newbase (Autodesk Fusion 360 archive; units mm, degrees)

design "newbase" references "arrayledrgbcircle"
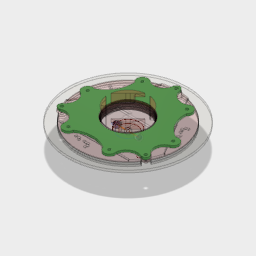
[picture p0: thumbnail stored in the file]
sketch "primary" plane through (0, 0, 0) normal (0, 1, 0) x axis (1, 0, 0)
  circle C1 centre (0, 0) radius 80
  circle C2 centre (0, 0) radius 27.5
  circle C3 centre (0, 0) radius 67
  circle C4 centre (0, 65) radius 1.6
  circle C5 centre (0, 65) radius 5
  circle C6 centre (-56.2917, -32.5) radius 5
  circle C7 centre (-56.2917, -32.5) radius 1.6
  circle C8 centre (56.2917, -32.5) radius 5
  circle C9 centre (56.2917, -32.5) radius 1.6
  point P4 (0, 0)
  point P5 (0, 65)
  dimension "d1" diameter C1 = 160
  dimension "d2" diameter C2 = 55
  dimension "d3" diameter C3 = 134
  dimension "d4" diameter C4 = 3.2
  dimension "d5" diameter C5 = 10
  dimension "d8" distance P4 P5 = 65
  dimension "d7" C-Pattern1-Angle = 360
extrude "Extrude1" new body sketch "primary" profile of C2 C3 C4 C5 C6 C7 C8 C9 along normal blind 5
extrude "Extrude1" new body sketch "primary" profile of C1 C3 C4 C5 C6 C7 C8 C9 against normal blind 3
component_from_bodies "Body->Comp"
component_insert "Component Insert"
position "Position1"
extrude "Extrude2" cut of existing geometry blind -1
position "Position2"
step "C-Pattern" TotalAngle 360
combine "Combine1"
extrude "Extrude3" add of existing geometry blind 1
extrude "Extrude4" cut of existing geometry blind -2
extrude "Extrude5" cut of existing geometry blind -2
extrude "Extrude6" cut of existing geometry blind -2
extrude "Extrude7" cut of existing geometry blind -2
extrude "Extrude8" cut of existing geometry blind -2
extrude "Extrude9" cut of existing geometry blind -2
extrude "Extrude10" cut of existing geometry blind -2
extrude "Extrude11" cut of existing geometry blind -2
extrude "Extrude12" cut of existing geometry blind -2
extrude "Extrude13" cut of existing geometry blind -2
extrude "Extrude14" cut of existing geometry blind -2
extrude "Extrude15" add of existing geometry blind 4 taper -15
extrude "Extrude16" cut of existing geometry blind 3 taper 50
extrude "Extrude17" cut of existing geometry blind -1.8
extrude "Extrude18" cut of existing geometry blind 1.8 taper -5
extrude "Extrude19" add of existing geometry blind 1.8 taper -10
sketch "innersplat" plane through (0, 5, 0) normal (0, 1, 0) x axis (-1, 0, 0)
  line L1 (64.1697, 18.1334) -> (62.973, 17.7903)
  line L2 (44.7956, 47.2415) -> (45.8929, 48.3778)
  line L3 (-46.8933, 45.6411) -> (44.7956, 47.2415)
  line L4 (-47.7888, 46.5059) -> (-46.8933, 45.6411)
  line L5 (-63.3102, 15.1734) -> (-64.8429, 15.5555)
  line L6 (-16.0797, -63.4314) -> (-63.3102, 15.1734)
  line L7 (-16.3808, -64.6393) -> (-16.0797, -63.4314)
  line L8 (18.5146, -62.4149) -> (18.9499, -63.9333)
  line L9 (62.973, 17.7903) -> (18.5146, -62.4149)
  line L10 (-16.4194, -63.4821) -> (-16.7651, -64.8686)
  line L11 (-63.5145, 14.8972) -> (-16.4194, -63.4821)
  line L12 (-65.2242, 15.3235) -> (-63.5145, 14.8972)
  line L13 (53.3921, 56.6004) -> (44.6586, 47.5566)
  line L14 (-46.7674, 45.9607) -> (-55.8112, 54.6942)
  line L15 (44.6586, 47.5566) -> (-46.7674, 45.9607)
  line L16 (-27.8174, 0) -> (0, 0)
  circle C1 centre (-56.2917, 32.5) radius 1.9174
  circle C2 centre (0, -65) radius 1.9174
  circle C3 centre (0, 0) radius 27.8174
  circle C4 centre (56.2917, 32.5) radius 1.9174
  arc A1 centre (0, 0) radius 66.6826 clockwise from (59.8334, 29.4369) to (64.1697, 18.1334)
  arc A2 centre (56.2917, 32.5) radius 4.6826 clockwise from (55.4098, 37.0988) to (59.8334, 29.4369)
  arc A3 centre (0, 0) radius 66.6826 clockwise from (45.8929, 48.3778) to (55.4098, 37.0988)
  arc A4 centre (0, 0) radius 66.6826 clockwise from (-55.4098, 37.0988) to (-47.7888, 46.5059)
  arc A5 centre (-56.2917, 32.5) radius 4.6826 clockwise from (-59.8334, 29.4369) to (-55.4098, 37.0988)
  arc A6 centre (0, 0) radius 66.6826 clockwise from (-64.8429, 15.5555) to (-59.8334, 29.4369)
  arc A7 centre (0, 0) radius 66.6826 clockwise from (-4.4236, -66.5357) to (-16.3808, -64.6393)
  arc A8 centre (0, -65) radius 4.6826 clockwise from (4.4236, -66.5357) to (-4.4236, -66.5357)
  arc A9 centre (0, 0) radius 66.6826 clockwise from (18.9499, -63.9333) to (4.4236, -66.5357)
  circle C5 centre (-26.0224, 50.8955) radius 7.5
  circle C6 centre (28.0714, 51.8397) radius 7.5
  circle C7 centre (-26.0224, 50.8955) radius 0.7062
  circle C8 centre (28.0714, 51.8397) radius 0.7062
  arc A10 centre (0.7926, 81.7658) radius 35.287 clockwise from (20.6067, 52.567) to (-18.6598, 52.3248)
  arc A11 centre (48.4412, 48.8033) radius 13.0949 clockwise from (54.1224, 37.0049) to (35.4894, 50.734)
  arc A12 centre (56.2917, 32.5) radius 5 clockwise from (60.2087, 29.3924) to (55.5589, 37.446)
  circle C9 centre (56.2917, 32.5) radius 5
  arc A13 centre (-56.2917, 32.5) radius 5 clockwise from (-55.5589, 37.446) to (-60.2087, 29.3924)
  arc A14 centre (-0.2565, 1.0456) radius 77.2302 clockwise from (-55.8112, 54.6942) to (53.3921, 56.6004)
  arc A15 centre (-48.1837, 50.7217) radius 14.9837 clockwise from (-33.293, 49.0548) to (-53.7741, 36.8199)
  arc A16 centre (-66.4855, 17.5497) radius 13.0949 clockwise from (-59.1084, 28.3689) to (-61.6816, 5.3677)
  circle C10 centre (-58.9302, -1.6094) radius 7.5
  arc A17 centre (-71.2075, -40.1965) radius 35.287 clockwise from (-55.8277, -8.4376) to (-35.9847, -42.3223)
  circle C11 centre (-31.0656, -47.9838) radius 7.5
  arc A18 centre (-19.8344, -67.0892) radius 14.9837 clockwise from (-25.8362, -53.36) to (-5, -64.9797)
  arc A19 centre (18.0443, -66.3529) radius 13.0949 clockwise from (4.986, -65.3738) to (26.1922, -56.1017)
  circle C12 centre (30.8589, -50.2304) radius 7.5
  arc A20 centre (70.415, -41.5693) radius 35.287 clockwise from (35.221, -44.1294) to (54.6445, -10.0025)
  circle C13 centre (57.088, -2.9117) radius 7.5
  arc A21 centre (68.0182, 16.3675) radius 14.9837 clockwise from (59.1292, 4.3052) to (58.774, 28.1597)
  circle C14 centre (30.8589, -50.2304) radius 1.778
  circle C15 centre (30.8589, -50.2304) radius 1.778
  arc A22 centre (-50.2895, -30.7888) radius 1.6618 clockwise from (-48.6559, -31.0934) to (-49.2638, -29.4814)
  arc A23 centre (-47.6302, -29.7859) radius 1.6618 clockwise from (-49.2638, -29.4814) to (-48.6559, -31.0934)
  arc A24 centre (-46.1884, -26.549) radius 1.6618 clockwise from (-46.0195, -24.8959) to (-47.8458, -26.4296)
  arc A25 centre (-47.6769, -24.7765) radius 1.6618 clockwise from (-47.8458, -26.4296) to (-48.5753, -23.3785)
  arc A26 centre (-48.7679, -21.7279) radius 1.6618 clockwise from (-48.5753, -23.3785) to (-47.8695, -23.126)
  arc A27 centre (-47.6769, -24.7765) radius 1.6618 clockwise from (-47.8695, -23.126) to (-46.0195, -24.8959)
  arc A28 centre (-52.9742, -17.4399) radius 1.6618 clockwise from (-51.611, -16.4895) to (-53.2282, -15.7977)
  arc A29 centre (-51.865, -14.8473) radius 1.6618 clockwise from (-53.2282, -15.7977) to (-51.611, -16.4895)
  circle C16 centre (-54.067, -11.4292) radius 1.6618
  arc A30 centre (0, 0) radius 67 clockwise from (-16.7651, -64.8686) to (-65.2242, 15.3235)
  circle C17 centre (-31.0656, -47.9838) radius 1.778
  circle C18 centre (-58.9302, -1.6094) radius 1.778
  circle C19 centre (-58.9302, -1.6094) radius 1.778
  circle C20 centre (0.1021, 53.2748) radius 0.47
  circle C21 centre (-1.9803, 56.1419) radius 0.47
  circle C22 centre (17.1355, 52.538) radius 0.47
  circle C23 centre (25.0284, 71.6947) radius 0.4955
  circle C24 centre (-0.8872, 73.5627) radius 0.47
  circle C25 centre (39.8169, 62.9684) radius 0.4955
  circle C26 centre (-22.8865, 67.7168) radius 0.47
  circle C27 centre (14.1431, 71.1576) radius 0.47
  circle C28 centre (37.5528, 65.8764) radius 0.4955
  circle C29 centre (-4.7526, 69.4306) radius 0.47
  circle C30 centre (-3.2754, 72.1238) radius 0.47
  circle C31 centre (-39.6032, 63.8855) radius 0.4955
  circle C32 centre (-32.038, 68.0652) radius 0.47
  circle C33 centre (-24.5993, 71.2435) radius 0.47
  circle C34 centre (6.7317, 73.6956) radius 0.47
  circle C35 centre (-46.2367, 51.9399) radius 0.47
  circle C36 centre (5.567, 53.0982) radius 0.47
  circle C37 centre (-43.1288, 62.1717) radius 0.4955
  circle C38 centre (-7.7707, 74.9667) radius 0.47
  circle C39 centre (-16.8801, 72.9024) radius 0.47
  circle C40 centre (-45.3191, 57.5838) radius 0.47
  circle C41 centre (16.0006, 71.317) radius 0.47
  circle C42 centre (-18.9678, 68.8014) radius 0.47
  circle C43 centre (23.2075, 68.5214) radius 0.4955
  circle C44 centre (11.3837, 54.5969) radius 0.47
  circle C45 centre (4.5303, 73.8722) radius 0.47
  circle C46 centre (47.2705, 58.0178) radius 0.4955
  circle C47 centre (31.5441, 65.5194) radius 0.4955
  circle C48 centre (-15.5504, 69.4961) radius 0.47
  circle C49 centre (45.2831, 55.4427) radius 0.4955
  circle C50 centre (13.0743, 52.3401) radius 0.47
  circle C51 centre (2.3814, 53.6777) radius 0.47
  circle C52 centre (-1.5192, 58.9464) radius 0.47
  circle C53 centre (28.0714, 51.8397) radius 1.778
  circle C54 centre (-26.0224, 50.8955) radius 1.778
  arc A31 centre (-0.2565, 1.0456) radius 77.2302 clockwise from (-55.8112, 54.6942) to (53.3921, 56.6004)
  circle C55 centre (28.0714, 51.8397) radius 1.778
  circle C56 centre (57.088, -2.9117) radius 1.778
  circle C57 centre (0, -65) radius 5
  dimension "d51" diameter C6 = 15
  dimension "d52" diameter C5 = 15
  dimension "d54" C-Pattern1-Angle = 360
extrude "Extrude1" new body sketch "innersplat" profile of C1 C2 C3 C4 A1 A2 A3 L3 A4 A5 A6 L6 L7 A7 A8 A9 L8 L9 C5 C6 A10 A11 A12 C9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 along normal blind 3
extrude "Extrude2" cut sketch "innersplat" profile of L6 L7 A7 A9 L8 L9 A16 A18 A19 C57 along normal blind 3
position "Position3"
combine "Combine2"
extrude "Extrude20" cut sketch "primary" profile of C2 C3 C5 C6 C8 along normal blind 2
place_component sketch "primary"
extrude "Extrude1" new body sketch "primary" profile of C2 C3 C5 C6 C8 against normal blind 3
sketch "Sketch1" plane through (0, 0, 0) normal (0, 1, 0) x axis (1, 0, 0)
  line L1 (-20.95, -20.95) -> (20.95, -20.95)
  line L2 (-20.95, 20.95) -> (-20.95, -20.95)
  line L3 (20.95, 20.95) -> (-20.95, 20.95)
  line L4 (20.95, -20.95) -> (20.95, 20.95)
  line L5 (-20.95, 20.95) -> (20.95, -20.95)
  line L6 (20.95, 20.95) -> (-20.95, -20.95)
  line L7 (20.95, 16.85) -> (16.85, 20.95)
  line L8 (-16.85, -20.95) -> (-20.95, -16.85)
  line L9 (0, -20.95) -> (0, 20.95)
  line L10 (16.85, -20.95) -> (20.95, -16.85)
  line L11 (-20.95, 16.85) -> (-16.85, 20.95)
  line L12 (-1.9, -1.6248) -> (-1.9, 1.6248)
  circle C1 centre (14.8, 14.8) radius 2.05
  circle C2 centre (0, 0) radius 11
  circle C3 centre (-14.8, 14.8) radius 2.05
  circle C4 centre (-14.8, -14.8) radius 2.05
  circle C5 centre (14.8, -14.8) radius 2.05
  circle C6 centre (0, 0) radius 4.5
  circle C7 centre (0, 0) radius 2.5
  point P2 (20.95, -20.95)
  point P3 (-20.95, -20.95)
  point P5 (20.95, 20.95)
  point P7 (14.8, 14.8)
  point P13 (20.95, 16.85)
  point P22 (0, 0)
  dimension "d1_2" distance P2 P3 = 41.9
  dimension "d2_2" distance P2 P5 = 41.9
  dimension "d3_2" diameter C1 = 4.1
  dimension "d4_2" distance L4 P7 = 6.15
  dimension "d5_2" diameter C2 = 22
  dimension "d8_2" distance L3 P13 = 4.1
  dimension "d9_2" diameter C6 = 9
  dimension "d10_2" diameter C7 = 5
  dimension "d11_2" distance P22 L12 = 1.9
  dimension "d7_2" C-Pattern1-Angle = 360
extrude "Extrude1" new body sketch "Sketch1" profile of L1 L2 L3 L4 C1 C2 C3 C4 C5 L7 L8 L10 L11 along normal blind 8 named "d12_2"
extrude "Extrude2" add sketch "Sketch1" profile of C2 C6 along normal blind 10 named "d14_2"
extrude "Extrude3" new body sketch "Sketch1" profile of C7 L12 along normal blind 22.3 named "d16_2"
extrude "Extrude4" add sketch "Sketch1" profile of C7 L12 along normal blind 11 named "d18_2"
extrude "Extrude5" add sketch "Sketch1" profile of C6 C7 along normal blind 7 named "d20_2"
extrude "Extrude6" add of existing geometry blind 10 named "d22_2"
sketch "Sketch2" plane through (0, 0, 0) normal (0, 1, 0) x axis (1, 0, 0)
  line L1 (-20.95, -20.95) -> (20.95, -20.95)
  line L2 (20.95, -20.95) -> (20.95, 20.95)
  line L3 (20.95, 16.85) -> (20.95, -16.85)
  line L4 (20.95, -16.85) -> (20.95, 16.85)
  line L5 (20.95, -14.0216) -> (14.0216, -20.95)
  line L6 (16.85, -20.95) -> (20.95, -16.85)
  line L7 (20.95, 20.95) -> (-20.95, -20.95)
  line L8 (0, -20.95) -> (0, 20.95)
  line L9 (0, 19) -> (0, -20.95)
  line L10 (-14.0216, 20.95) -> (-20.95, 14.0216)
  line L11 (14.0216, 20.95) -> (20.95, 14.0216)
  line L12 (-20.95, -14.0216) -> (-14.0216, -20.95)
  line L13 (-20.95, -14.0216) -> (-20.95, 14.0216)
  line L14 (14.0216, -20.95) -> (-14.0216, -20.95)
  line L15 (20.95, 14.0216) -> (20.95, -14.0216)
  line L16 (-14.0216, 20.95) -> (14.0216, 20.95)
  dimension "d24_2" angle L1 L5 = 45
  dimension "d25_2" distance L5 L6 = 2
extrude "Extrude7" add sketch "Sketch2" profile of L1 L2 L3 L4 L5 L8 L10 L11 L12 L13 L14 L15 L16 against normal blind 30 named "d26_2"
work_plane "WorkPlane1" sketch "Sketch1" AlongDistance -15 named "d28_2"
split "Split1"
sketch "Sketch3" plane through (0, -15, 0) normal (0, 1, 0) x axis (1, 0, 0)
  line L1 (0, 35) -> (0, -30)
copy_paste_bodies "CopyPasteBodies1"
move "Move1" RotateAngle 180 named "d29_2"
work_plane "WorkPlane2" AlongDistance 0 named "d30_2"
combine "Combine1"
combine "Combine2"
combine "Combine3"
combine "Combine4"
sketch "Sketch4" plane through (0, -38, 0) normal (0, -1, 0) x axis (1, 0, 0)
  circle C1 centre (0, 0) radius 19.3452
extrude "Extrude8" cut sketch "Sketch4" along normal blind 30 named "d31_2"
sketch "Sketch5" plane through (0, 0, -20.95) normal (0, 0, -1) x axis (-1, 0, 0)
  line L1 (-16.85, -30) -> (-14.0216, -30)
  line L2 (-16.85, -38) -> (-16.85, -30)
  line L3 (16.85, -38) -> (-16.85, -38)
  line L4 (16.85, -30) -> (16.85, -38)
  line L5 (14.0216, -30) -> (16.85, -30)
  line L6 (14.0216, 0) -> (14.0216, -30)
  line L7 (16.85, 0) -> (14.0216, 0)
  line L8 (16.85, 8) -> (16.85, 0)
  line L9 (-16.85, 8) -> (16.85, 8)
  line L10 (-16.85, 0) -> (-16.85, 8)
  line L11 (-14.0216, 0) -> (-16.85, 0)
  line L12 (-14.0216, -30) -> (-14.0216, 0)
  line L13 (3.75, -30) -> (-3.75, -30)
  line L14 (3.75, -37.5) -> (3.75, -30)
  line L15 (-3.75, -37.5) -> (3.75, -37.5)
  line L16 (-3.75, -30) -> (-3.75, -37.5)
  line L17 (14.0216, -30) -> (-14.0216, -30)
  line L18 (0, -30) -> (0, -37.5)
  point P14 (-3.75, -30)
  point P15 (3.75, -30)
  point P16 (3.75, -37.5)
  dimension "d33_2" distance P14 P15 = 7.5
  dimension "d34_2" distance P15 P16 = 7.5
  dimension "d35_2" distance L3 L15 = 0.5
  dimension "d38_2" distance L4 L14 = 13.1
  dimension "d39_2" = 13.2
extrude "Extrude9" cut sketch "Sketch5" profile of L13 L14 L15 L16 against normal blind 1 named "d40_2"
revolve "Revolve1" AlongAngle 90
extrude "Extrude1" cut of existing geometry blind 235
position "Position4"
sketch "Sketch6" plane through (0, -3, 0) normal (0, -1, 0) x axis (1, 0, 0)
  line L1 (2.8991, -26.7286) -> (26.7286, -2.8991)
  line L2 (26.7286, -2.8991) -> (2.8991, -26.7286)
  line L3 (26.7286, -2.8991) -> (2.8991, -26.7286)
  line L4 (2.8991, 26.7286) -> (26.7286, 2.8991)
  line L5 (2.8991, 26.7286) -> (-2.8991, 26.7286)
  line L6 (-2.8991, 26.7286) -> (2.8991, 26.7286)
  line L7 (-29.6278, 0) -> (0, 29.6278)
  line L8 (-2.8991, 26.7286) -> (-26.7286, 2.8991)
  line L9 (-2.8991, -26.7286) -> (-26.7286, -2.8991)
  circle C1 centre (0, 0) radius 27.5
  arc A1 centre (0, 0) radius 67 clockwise from (-4.6497, -66.8385) to (-60.2087, 29.3924)
  arc A2 centre (0, -65) radius 5 clockwise from (-4.6497, -66.8385) to (4.6497, -66.8385)
  arc A3 centre (0, 0) radius 67 clockwise from (60.2087, 29.3924) to (4.6497, -66.8385)
  arc A4 centre (56.2917, 32.5) radius 5 clockwise from (60.2087, 29.3924) to (55.5589, 37.446)
  arc A5 centre (0, 0) radius 67 clockwise from (-55.5589, 37.446) to (55.5589, 37.446)
  arc A6 centre (-56.2917, 32.5) radius 5 clockwise from (-55.5589, 37.446) to (-60.2087, 29.3924)
  circle C2 centre (0, 0) radius 26.5
  circle C3 centre (0, 0) radius 21.0524
  dimension "d75" diameter C2 = 53
extrude "Extrude1" new body sketch "Sketch6" profile of C2 C3 L1 L2 L3 L4 L7 L8 L9 against normal blind 23
remove_instance "RemoveInstance1"
sketch "Sketch7" plane through (-24.7286, 0, 0) normal (-1, 0, 0) x axis (0, 0, 1)
  line L1 (-4.8991, 16) -> (-4.8991, 46)
  line L2 (4.8991, 16) -> (-4.8991, 16)
  line L3 (4.8991, 46) -> (4.8991, 16)
  line L4 (-4.8991, 46) -> (4.8991, 46)
  line L5 (13.3474, 20) -> (13.3474, -3)
  line L6 (13.3474, 16) -> (-4.8991, 16)
  line L7 (13.3474, 8) -> (13.3474, 16)
  line L8 (-26.7286, 8) -> (-2.8991, 8)
  line L9 (-4.8991, 8) -> (13.3474, 8)
  line L10 (-4.8991, 16) -> (-4.8991, 8)
  line L11 (4.2241, 8) -> (4.2241, 16)
  line L12 (5.7241, 8) -> (5.7241, 16)
  point P16 (5.7241, 16)
  point P17 (5.7241, 8)
  dimension "d78" distance P16 P17 = 8
  dimension "d79" distance L11 L12 = 1.5
revolve "Revolve1" sketch "Sketch7" AlongAngle 360
circular_pattern "C-Pattern1" TotalAngle 360
combine "Combine1"
combine "Combine2"
combine "Combine3"
combine "Combine4"
combine "Combine5"
extrude "Extrude2" cut of existing geometry blind -3
extrude "Extrude3" cut of existing geometry blind -3
extrude "Extrude4" cut of existing geometry blind -3
extrude "Extrude5" cut of existing geometry blind -3
extrude "Extrude6" add sketch "innersplat" profile of C3 along normal blind 3 and against normal blind 11
sketch "Sketch8" plane through (0, 0, 0) normal (1, 0, 0) x axis (0, 0, -1)
  line L1 (66.8385, -3) -> (-29.3924, -3)
  line L2 (-37.446, -3) -> (-27.5, -3)
  line L3 (-37.5287, -3) -> (-27.5287, -3)
  line L4 (-36, -6) -> (-37.5287, -3)
  line L5 (27.8174, -6) -> (-27.8174, -6)
  line L6 (-27.5199, -6) -> (-36, -6)
  line L7 (-27.5287, -3) -> (-27.5199, -6)
  point P6 (-27.5287, -3)
  point P7 (-37.5287, -3)
  dimension "d95" distance P6 P7 = 10
revolve "Revolve2" sketch "Sketch8" AlongAngle 360
thread "Thread1"
sketch "Innersplat.dxf" plane through (0, 8, 0) normal (0, 1, 0) x axis (-1, 0, 0)
  arc A1 centre (18.0443, -66.3529) radius 13.0949 clockwise from (4.986, -65.3738) to (26.1922, -56.1017)
  arc A2 centre (30.8589, -50.2304) radius 7.5 clockwise from (35.221, -44.1294) to (26.1922, -56.1017)
  arc A3 centre (70.415, -41.5693) radius 35.287 clockwise from (35.221, -44.1294) to (54.6445, -10.0025)
  arc A4 centre (57.088, -2.9117) radius 7.5 clockwise from (59.1292, 4.3052) to (54.6445, -10.0025)
  arc A5 centre (68.0182, 16.3675) radius 14.9837 clockwise from (59.1292, 4.3052) to (58.774, 28.1597)
  arc A6 centre (56.2917, 32.5) radius 5 clockwise from (59.9841, 29.1287) to (58.774, 28.1597)
  arc A7 centre (0, 0) radius 66.6826 clockwise from (59.8334, 29.4369) to (59.9841, 29.1287)
  arc A8 centre (56.2917, 32.5) radius 4.6826 clockwise from (55.4098, 37.0988) to (59.8334, 29.4369)
  arc A9 centre (0, 0) radius 66.6826 clockwise from (55.2182, 37.3834) to (55.4098, 37.0988)
  arc A10 centre (56.2917, 32.5) radius 5 clockwise from (54.1224, 37.0049) to (55.2182, 37.3834)
  arc A11 centre (48.4412, 48.8033) radius 13.0949 clockwise from (54.1224, 37.0049) to (35.4894, 50.734)
  arc A12 centre (28.0714, 51.8397) radius 7.5 clockwise from (20.6067, 52.567) to (35.4894, 50.734)
  arc A13 centre (0.7926, 81.7658) radius 35.287 clockwise from (20.6067, 52.567) to (-18.6598, 52.3248)
  arc A14 centre (-26.0224, 50.8955) radius 7.5 clockwise from (-33.293, 49.0548) to (-18.6598, 52.3248)
  arc A15 centre (-48.1837, 50.7217) radius 14.9837 clockwise from (-33.293, 49.0548) to (-53.7741, 36.8199)
  arc A16 centre (-56.2917, 32.5) radius 5 clockwise from (-55.2182, 37.3834) to (-53.7741, 36.8199)
  arc A17 centre (0, 0) radius 66.6826 clockwise from (-55.4098, 37.0988) to (-55.2182, 37.3834)
  arc A18 centre (-56.2917, 32.5) radius 4.6826 clockwise from (-59.8334, 29.4369) to (-55.4098, 37.0988)
  arc A19 centre (0, 0) radius 66.6826 clockwise from (-59.9841, 29.1287) to (-59.8334, 29.4369)
  arc A20 centre (-56.2917, 32.5) radius 5 clockwise from (-59.1084, 28.3689) to (-59.9841, 29.1287)
  arc A21 centre (-66.4855, 17.5497) radius 13.0949 clockwise from (-59.1084, 28.3689) to (-61.6816, 5.3677)
  arc A22 centre (-58.9302, -1.6094) radius 7.5 clockwise from (-55.8277, -8.4376) to (-61.6816, 5.3677)
  arc A23 centre (-71.2075, -40.1965) radius 35.287 clockwise from (-55.8277, -8.4376) to (-35.9847, -42.3223)
  arc A24 centre (-31.0656, -47.9838) radius 7.5 clockwise from (-25.8362, -53.36) to (-35.9847, -42.3223)
  arc A25 centre (-19.8344, -67.0892) radius 14.9837 clockwise from (-25.8362, -53.36) to (-5, -64.9797)
  arc A26 centre (0, -65) radius 5 clockwise from (-4.7659, -66.5121) to (-5, -64.9797)
  arc A27 centre (0, 0) radius 66.6826 clockwise from (-4.4236, -66.5357) to (-4.7659, -66.5121)
  arc A28 centre (0, -65) radius 4.6826 clockwise from (4.4236, -66.5357) to (-4.4236, -66.5357)
  arc A29 centre (0, 0) radius 66.6826 clockwise from (4.7659, -66.5121) to (4.4236, -66.5357)
  arc A30 centre (0, -65) radius 5 clockwise from (4.986, -65.3738) to (4.7659, -66.5121)
  circle C1 centre (30.8589, -50.2304) radius 1.778
  circle C2 centre (56.2917, 32.5) radius 1.9174
  circle C3 centre (-56.2917, 32.5) radius 1.9174
  circle C4 centre (0, 0) radius 27.8174
  circle C5 centre (28.0714, 51.8397) radius 1.778
  circle C6 centre (57.088, -2.9117) radius 1.778
  circle C7 centre (0, -65) radius 1.9174
  circle C8 centre (-31.0656, -47.9838) radius 1.778
  circle C9 centre (-58.9302, -1.6094) radius 1.778
  circle C10 centre (-26.0224, 50.8955) radius 1.778
sketch "Outerring.dxf" plane through (0, 2, 0) normal (0, 1, 0) x axis (-1, 0, 0)
  circle C1 centre (0, -65) radius 1.6
  circle C2 centre (56.2917, 32.5) radius 1.6
  arc A1 centre (0, 0) radius 67 clockwise from (60.2087, 29.3924) to (4.6497, -66.8385)
  arc A2 centre (0, -65) radius 5 clockwise from (-4.6497, -66.8385) to (4.6497, -66.8385)
  arc A3 centre (0, 0) radius 67 clockwise from (-4.6497, -66.8385) to (-60.2087, 29.3924)
  arc A4 centre (-56.2917, 32.5) radius 5 clockwise from (-55.5589, 37.446) to (-60.2087, 29.3924)
  arc A5 centre (0, 0) radius 67 clockwise from (-55.5589, 37.446) to (55.5589, 37.446)
  arc A6 centre (56.2917, 32.5) radius 5 clockwise from (60.2087, 29.3924) to (55.5589, 37.446)
  circle C3 centre (-56.2917, 32.5) radius 1.6
  circle C4 centre (0, 0) radius 80
sketch "Decoring.dxf" plane through (0, 0, 0) normal (0, 1, 0) x axis (-1, 0, 0)
  circle C1 centre (0, 0) radius 27.5
  arc A1 centre (0, 0) radius 67 clockwise from (60.2087, 29.3924) to (4.6497, -66.8385)
  arc A2 centre (56.2917, 32.5) radius 5 clockwise from (60.2087, 29.3924) to (55.5589, 37.446)
  arc A3 centre (0, 0) radius 67 clockwise from (-55.5589, 37.446) to (55.5589, 37.446)
  arc A4 centre (-56.2917, 32.5) radius 5 clockwise from (-55.5589, 37.446) to (-60.2087, 29.3924)
  arc A5 centre (0, 0) radius 67 clockwise from (-4.6497, -66.8385) to (-60.2087, 29.3924)
  arc A6 centre (0, -65) radius 5 clockwise from (-4.6497, -66.8385) to (4.6497, -66.8385)
sketch "Sketch12" plane through (0, -6, 0) normal (0, -1, 0) x axis (1, 0, 0)
  circle C1 centre (0, 0) radius 36
  circle C2 centre (0, 0) radius 15
  circle C3 centre (0, 0) radius 1.6
  dimension "d97" diameter C2 = 30
  dimension "d98" diameter C3 = 3.2
extrude "Extrude1" new body sketch "Sketch12" profile of C2 C3 along normal blind 3
sketch "Sketch13" plane through (0, -6, 0) normal (0, -1, 0) x axis (1, 0, 0)
  circle C1 centre (0, 0) radius 36
sketch "Sketch14" plane through (0, -9, 0) normal (0, -1, 0) x axis (1, 0, 0)
  line L1 (-12.5, 0) -> (-15, 0)
  line L2 (12.5, 0.01) -> (15, 0.01)
  line L3 (-20, 0) -> (-15, 0)
  line L4 (-20, -3) -> (-20, 0)
  line L5 (-14.6969, -3) -> (-20, -3)
  line L6 (15, 0.01) -> (-15, 0)
  line L7 (-14.6989, 3.0002) -> (-20.002, 2.9967)
  line L8 (-20.002, 2.9967) -> (-20, -0.0033)
  line L9 (-20, -0.0033) -> (-15, 0)
  line L10 (-15, 0) -> (-12.5, 0.0017)
  line L11 (15, 0.01) -> (12.5, 0.0084)
  line L12 (-15, 0) -> (-20, 0)
  circle C1 centre (0, 0) radius 1.6
  circle C2 centre (0, 0) radius 15
  arc A1 centre (0, 0) radius 12.5 clockwise from (12.5, 0.01) to (-12.5, 0)
  circle C3 centre (15, 0.01) radius 2.5
  arc A2 centre (0, 0.01) radius 12.5 clockwise from (-12.5, 0.0017) to (12.5, 0.0084)
  arc A3 centre (0.2129, -0.0113) radius 15.2129 clockwise from (-15, 0) to (-14.6989, 3.0002)
  point P4 (-15, 0)
  point P5 (-12.5, 0)
  point P6 (15, 0.01)
  point P7 (12.5, 0.01)
  point P11 (-20, 0)
  dimension "d101" distance P4 P5 = 2.5
  dimension "d102" distance P6 P7 = 2.5
  dimension "d103" diameter C3 = 5
  dimension "d108" distance P4 P11 = 5
extrude "Extrude2" add sketch "Sketch14" profile of C2 L1 L2 A1 C3 along normal blind 7
extrude "Extrude3" add of existing geometry blind 15
extrude "Extrude4" add sketch "Sketch14" profile of C2 L3 L4 L5 along normal blind 22
extrude "Extrude5" new body sketch "Sketch14" profile of C2 C3 L3 A2 L7 L8 L10 L12 A3 along normal blind 22
extrude "Extrude6" cut sketch "Sketch14" profile of C2 L2 C3 L11 along normal blind 22
extrude "Extrude7" add sketch "Sketch14" profile of C2 L2 C3 L11 along normal blind 7
sketch "Sketch1" plane through (0, -16, 0) normal (0, -1, 0) x axis (1, 0, 0)
  line L1 (15, 0.01) -> (12.5, 0.01)
  line L2 (12.5, 0.0084) -> (15, 0.01)
  arc A1 centre (15, 0.01) radius 2.5 clockwise from (14.7933, -2.4814) to (12.5, 0.0084)
  arc A2 centre (15, 0.01) radius 2.5 clockwise from (12.5, 0.01) to (14.7933, -2.4814)
extrude "Extrude9" new body sketch "Sketch1" along normal blind 8
combine "Combine1"
sketch "Sketch2" plane through (0, -24, 0) normal (0, -1, 0) x axis (1, 0, 0)
  line L1 (12.5, 0.0084) -> (15, 0.01)
  line L2 (15, 0.01) -> (12.5, 0.01)
  arc A1 centre (15, 0.01) radius 2.5 clockwise from (14.79, 2.5012) to (12.5, 0.0084)
  arc A2 centre (15, 0.01) radius 2.5 clockwise from (12.5, 0.01) to (14.79, 2.5012)
extrude "Extrude10" add sketch "Sketch2" along normal blind 7
extrude "Extrude8" add of existing geometry blind 8
sketch "Sketch1" plane through (0, 0, 0) normal (0, 1, 0) x axis (1, 0, 0)
  line L1 (-20.95, -20.95) -> (20.95, -20.95)
  line L2 (-20.95, 20.95) -> (-20.95, -20.95)
  line L3 (20.95, 20.95) -> (-20.95, 20.95)
  line L4 (20.95, -20.95) -> (20.95, 20.95)
  line L5 (-20.95, 20.95) -> (20.95, -20.95)
  line L6 (20.95, 20.95) -> (-20.95, -20.95)
  line L7 (20.95, 16.85) -> (16.85, 20.95)
  line L8 (-16.85, -20.95) -> (-20.95, -16.85)
  line L9 (0, -20.95) -> (0, 20.95)
  line L10 (16.85, -20.95) -> (20.95, -16.85)
  line L11 (-20.95, 16.85) -> (-16.85, 20.95)
  line L12 (-1.9, -1.6248) -> (-1.9, 1.6248)
  circle C1 centre (14.8, 14.8) radius 2.05
  circle C2 centre (0, 0) radius 11
  circle C3 centre (-14.8, 14.8) radius 2.05
  circle C4 centre (-14.8, -14.8) radius 2.05
  circle C5 centre (14.8, -14.8) radius 2.05
  circle C6 centre (0, 0) radius 4.5
  circle C7 centre (0, 0) radius 2.5
  point P2 (20.95, -20.95)
  point P3 (-20.95, -20.95)
  point P5 (20.95, 20.95)
  point P7 (14.8, 14.8)
  point P13 (20.95, 16.85)
  point P22 (0, 0)
  dimension "d1_1" distance P2 P3 = 41.9
  dimension "d2_1" distance P2 P5 = 41.9
  dimension "d3_1" diameter C1 = 4.1
  dimension "d4_1" distance L4 P7 = 6.15
  dimension "d5_1" diameter C2 = 22
  dimension "d8_1" distance L3 P13 = 4.1
  dimension "d9_1" diameter C6 = 9
  dimension "d10_1" diameter C7 = 5
  dimension "d11_1" distance P22 L12 = 1.9
  dimension "d7_1" C-Pattern1-Angle = 360
extrude "Extrude1" new body sketch "Sketch1" profile of L1 L2 L3 L4 C1 C2 C3 C4 C5 L7 L8 L10 L11 along normal blind 8 named "d12_1"
extrude "Extrude2" add sketch "Sketch1" profile of C2 C6 along normal blind 10 named "d14_1"
extrude "Extrude3" new body sketch "Sketch1" profile of C7 L12 along normal blind 22.3 named "d16_1"
extrude "Extrude4" add sketch "Sketch1" profile of C7 L12 along normal blind 11 named "d18_1"
extrude "Extrude5" add sketch "Sketch1" profile of C6 C7 along normal blind 7 named "d20_1"
extrude "Extrude6" add of existing geometry blind 10 named "d22_1"
sketch "Sketch2" plane through (0, 0, 0) normal (0, 1, 0) x axis (1, 0, 0)
  line L1 (-20.95, -20.95) -> (20.95, -20.95)
  line L2 (20.95, -20.95) -> (20.95, 20.95)
  line L3 (20.95, 16.85) -> (20.95, -16.85)
  line L4 (20.95, -16.85) -> (20.95, 16.85)
  line L5 (20.95, -14.0216) -> (14.0216, -20.95)
  line L6 (16.85, -20.95) -> (20.95, -16.85)
  line L7 (20.95, 20.95) -> (-20.95, -20.95)
  line L8 (0, -20.95) -> (0, 20.95)
  line L9 (0, 19) -> (0, -20.95)
  line L10 (-14.0216, 20.95) -> (-20.95, 14.0216)
  line L11 (14.0216, 20.95) -> (20.95, 14.0216)
  line L12 (-20.95, -14.0216) -> (-14.0216, -20.95)
  line L13 (-20.95, -14.0216) -> (-20.95, 14.0216)
  line L14 (14.0216, -20.95) -> (-14.0216, -20.95)
  line L15 (20.95, 14.0216) -> (20.95, -14.0216)
  line L16 (-14.0216, 20.95) -> (14.0216, 20.95)
  dimension "d24_1" angle L1 L5 = 45
  dimension "d25_1" distance L5 L6 = 2
extrude "Extrude7" add sketch "Sketch2" profile of L1 L2 L3 L4 L5 L8 L10 L11 L12 L13 L14 L15 L16 against normal blind 30 named "d26_1"
work_plane "WorkPlane1" sketch "Sketch1" AlongDistance -15 named "d28_1"
split "Split1"
sketch "Sketch3" plane through (0, -15, 0) normal (0, 1, 0) x axis (1, 0, 0)
  line L1 (0, 35) -> (0, -30)
copy_paste_bodies "CopyPasteBodies1"
move "Move1" RotateAngle 180 named "d29_1"
work_plane "WorkPlane2" AlongDistance 0 named "d30_1"
combine "Combine1"
combine "Combine2"
combine "Combine3"
combine "Combine4"
sketch "Sketch4" plane through (0, -38, 0) normal (0, -1, 0) x axis (1, 0, 0)
  circle C1 centre (0, 0) radius 19.3452
extrude "Extrude8" cut sketch "Sketch4" along normal blind 30 named "d31_1"
sketch "Sketch5" plane through (0, 0, -20.95) normal (0, 0, -1) x axis (-1, 0, 0)
  line L1 (-16.85, -30) -> (-14.0216, -30)
  line L2 (-16.85, -38) -> (-16.85, -30)
  line L3 (16.85, -38) -> (-16.85, -38)
  line L4 (16.85, -30) -> (16.85, -38)
  line L5 (14.0216, -30) -> (16.85, -30)
  line L6 (14.0216, 0) -> (14.0216, -30)
  line L7 (16.85, 0) -> (14.0216, 0)
  line L8 (16.85, 8) -> (16.85, 0)
  line L9 (-16.85, 8) -> (16.85, 8)
  line L10 (-16.85, 0) -> (-16.85, 8)
  line L11 (-14.0216, 0) -> (-16.85, 0)
  line L12 (-14.0216, -30) -> (-14.0216, 0)
  line L13 (3.75, -30) -> (-3.75, -30)
  line L14 (3.75, -37.5) -> (3.75, -30)
  line L15 (-3.75, -37.5) -> (3.75, -37.5)
  line L16 (-3.75, -30) -> (-3.75, -37.5)
  line L17 (14.0216, -30) -> (-14.0216, -30)
  line L18 (0, -30) -> (0, -37.5)
  point P14 (-3.75, -30)
  point P15 (3.75, -30)
  point P16 (3.75, -37.5)
  dimension "d33_1" distance P14 P15 = 7.5
  dimension "d34_1" distance P15 P16 = 7.5
  dimension "d35_1" distance L3 L15 = 0.5
  dimension "d38_1" distance L4 L14 = 13.1
  dimension "d39_1" = 13.2
extrude "Extrude9" cut sketch "Sketch5" profile of L13 L14 L15 L16 against normal blind 1 named "d40_1"
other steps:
base_feature "Base Feature1"
base_feature "Base Feature1"
base_feature "Base Feature1"
create_component "CreateComponent1"
create_component "CreateComponent2"
remove_body "RemoveBody1"
create_component "CreateComponent3"
create_component "CreateComponent4"
create_component "CreateComponent5" sketch "primary"
create_component "CreateComponent6"
create_component "CreateComponent8"
create_component "CreateComponent9"
create_component "CreateComponent10"

design "arrayledrgbcircle"
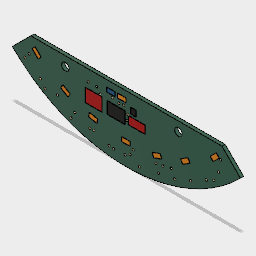
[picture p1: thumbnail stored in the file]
part number: 1uF
part number: ATTINY44-SSU
part number: 5v
part number: isp
part number: power
part number: 499
part number: rgb
pcb "PCB" BoardHeight 1.57
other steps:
extrude "Extrude1" new body sketch "Sketch1" blind 0.1 bodies "C1206FAB"
extrude "Extrude1" new body sketch "Sketch1" blind 0.1 bodies "SOIC14"
extrude "Extrude1" new body sketch "Sketch1" blind 0.1 bodies "SOT23"
extrude "Extrude1" new body sketch "Sketch1" blind 0.1 bodies "2X03SMD"
extrude "Extrude1" new body sketch "Sketch1" blind 0.1 bodies "2X02SMD"
extrude "Extrude1" new body sketch "Sketch1" blind 0.1 bodies "R1206FAB"
extrude "Extrude1" new body sketch "Sketch1" blind 0.1 bodies "P-LCC-4"
extrude "Extrude1" new body sketch "Sketch1" blind 1.57 bodies "Board"
extrude "Extrude4" sketch "Sketch4" blind 1.57
create_component "CreateComponent1"
create_component "CreateComponent1"
sketch "Sketch1"
  line L1 (101.346, 32.258) -> (9.906, 32.258)
  line L2 (9.906, 32.258) -> (1.016, 23.368)
  line L3 (110.236, 23.368) -> (101.346, 32.258)
  arc A1 centre (55.626, 77.978) radius 77.2302 clockwise from (110.236, 23.368) to (1.016, 23.368)
  circle C1 centre (26.416, 27.686) radius 1.778
  circle C2 centre (80.518, 27.686) radius 1.778
create_component "CreateComponent2" sketch "Sketch1"
sketch "Sketch1"
  line L1 (2.032, -1.016) -> (-2.032, -1.016)
  line L2 (2.032, 1.016) -> (2.032, -1.016)
  line L3 (-2.032, 1.016) -> (2.032, 1.016)
  line L4 (-2.032, -1.016) -> (-2.032, 1.016)
create_component "CreateComponent3" sketch "Sketch1"
sketch "Sketch1"
  line L1 (4.267, -2.858) -> (-4.267, -2.858)
  line L2 (4.267, 2.858) -> (4.267, -2.858)
  line L3 (-4.267, 2.858) -> (4.267, 2.858)
  line L4 (-4.267, -2.858) -> (-4.267, 2.858)
create_component "CreateComponent4" sketch "Sketch1"
sketch "Sketch1"
  line L1 (1.422, -1.295) -> (-1.422, -1.295)
  line L2 (1.422, 1.295) -> (1.422, -1.295)
  line L3 (-1.422, 1.295) -> (1.422, 1.295)
  line L4 (-1.422, -1.295) -> (-1.422, 1.295)
create_component "CreateComponent5" sketch "Sketch1"
sketch "Sketch1"
  line L1 (4.19, -3.175) -> (-3.81, -3.175)
  line L2 (4.19, 3.175) -> (4.19, -3.175)
  line L3 (-3.81, 3.175) -> (4.19, 3.175)
  line L4 (-3.81, -3.175) -> (-3.81, 3.175)
create_component "CreateComponent6" sketch "Sketch1"
sketch "Sketch1"
  line L1 (4.19, -1.905) -> (-3.81, -1.905)
  line L2 (4.19, 1.905) -> (4.19, -1.905)
  line L3 (-3.81, 1.905) -> (4.19, 1.905)
  line L4 (-3.81, -1.905) -> (-3.81, 1.905)
create_component "CreateComponent7" sketch "Sketch1"
sketch "Sketch1"
  line L1 (2.032, -1.016) -> (-2.032, -1.016)
  line L2 (2.032, 1.016) -> (2.032, -1.016)
  line L3 (-2.032, 1.016) -> (2.032, 1.016)
  line L4 (-2.032, -1.016) -> (-2.032, 1.016)
create_component "CreateComponent8" sketch "Sketch1"
sketch "Sketch1"
  line L1 (1.4, -1.8) -> (-2.032, -1.8)
  line L2 (1.4, 1.8) -> (1.4, -1.8)
  line L3 (-2.032, 1.8) -> (1.4, 1.8)
  line L4 (-2.032, -1.8) -> (-2.032, 1.8)
canvas "Canvas5"
canvas "Canvas6"
sketch "Sketch4"
  circle C1 centre (43.053, 24.638) radius 0.47
  circle C2 centre (48.895, 26.035) radius 0.47
  circle C3 centre (100.711, 26.289) radius 0.47
  circle C4 centre (97.425, 16.113) radius 0.4955
  circle C5 centre (47.371, 5.461) radius 0.47
  circle C6 centre (61.849, 3.937) radius 0.47
  circle C7 centre (78.74, 7.366) radius 0.47
  circle C8 centre (70.993, 5.842) radius 0.47
  circle C9 centre (86.233, 10.414) radius 0.47
  circle C10 centre (99.695, 20.662) radius 0.47
  circle C11 centre (93.87, 14.461) radius 0.4955
  circle C12 centre (38.145, 8.001) radius 0.47
  circle C13 centre (57.404, 6.858) radius 0.47
  circle C14 centre (73.152, 9.906) radius 0.47
  circle C15 centre (58.928, 9.525) radius 0.47
  circle C16 centre (30.988, 10.922) radius 0.4955
  circle C17 centre (16.691, 13.817) radius 0.4955
  circle C18 centre (40.005, 8.128) radius 0.47
  circle C19 centre (49.569, 5.246) radius 0.47
  circle C20 centre (77.089, 10.922) radius 0.47
  circle C21 centre (7.112, 21.844) radius 0.4955
  circle C22 centre (14.478, 16.764) radius 0.4955
  circle C23 centre (22.705, 14.069) radius 0.4955
  circle C24 centre (54.991, 5.461) radius 0.47
  circle C25 centre (69.723, 9.271) radius 0.47
  circle C26 centre (29.112, 7.781) radius 0.4955
  circle C27 centre (9.144, 24.384) radius 0.4955
  circle C28 centre (37.338, 26.797) radius 0.47
  circle C29 centre (41.402, 26.924) radius 0.47
  circle C30 centre (56.388, 22.86) radius 0.47
  circle C31 centre (52.07, 25.4) radius 0.47
  circle C32 centre (54.356, 25.763) radius 0.47
  circle C33 centre (55.878, 20.064) radius 0.47
as_built_joint "As-built3"
named bodies: "Board", "C1206FAB", "SOIC14", "SOT23", "2X03SMD", "2X02SMD", "R1206FAB", "P-LCC-4"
